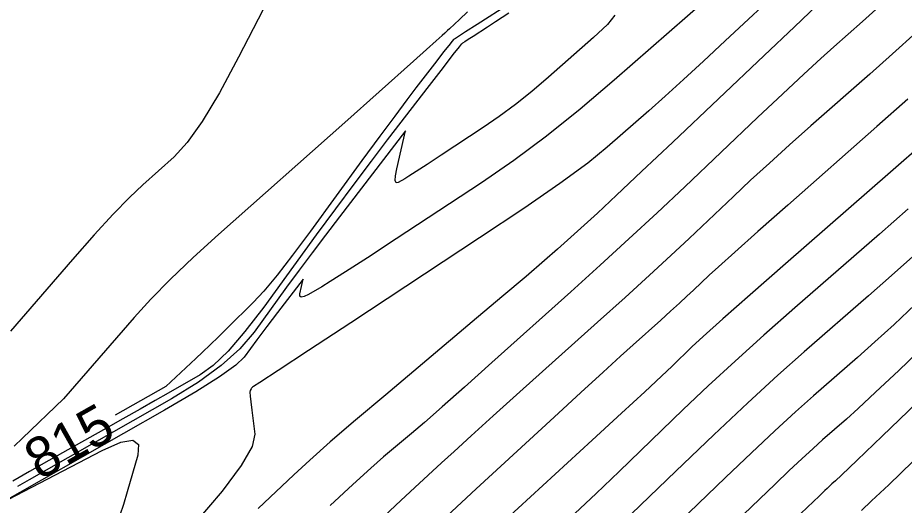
# Model space of a CAD drawing. Extents: x 2079879 to 2092887, y 778083 to 784051.
# Drawn here: x 2084103 to 2084164.7, y 780949.2 to 780983.2 of the extents above; entities that cross this region are included whole.
import ezdxf

# ---------------------------------------------------------------- set-up
doc = ezdxf.new("R2010")
doc.units = 0
doc.layers.add('DT_X_Contour_Major', color=7, linetype='Continuous')
doc.layers.add('DT_X_Contour_Minor', color=7, linetype='Continuous')

msp = doc.modelspace()

# ---------------------------------------------------------------- linework, layer by layer
at = {"layer": 'DT_X_Contour_Major'}
for points in [[(2084139.433, 780985.629), (2084134.941, 780982.739), (2084134.131, 780982.217), (2084133.625, 780981.892), (2084133.424, 780981.763), (2084133.294, 780981.679), (2084133.183, 780981.563), (2084132.95, 780981.28), (2084132.593, 780980.828), (2084132.114, 780980.208), (2084130.671, 780978.332), (2084130.03, 780977.487), (2084129.19, 780976.358), (2084128.151, 780974.945), (2084126.912, 780973.249), (2084123.344, 780968.347), (2084122.09, 780966.657), (2084121.005, 780965.261), (2084120.088, 780964.161), (2084119.339, 780963.357), (2084117.567, 780961.604), (2084116.93, 780960.977), (2084116.347, 780960.41), (2084115.818, 780959.903), (2084115.344, 780959.456), (2084113.259, 780957.508), (2084109.749, 780955.525)], [(2084158.593, 780984.075), (2084157.019, 780982.582), (2084154.905, 780980.576), (2084148.551, 780974.544), (2084146.379, 780972.486), (2084144.627, 780970.836), (2084143.295, 780969.594), (2084142.383, 780968.759), (2084140.513, 780967.079), (2084139.617, 780966.29), (2084138.332, 780965.183), (2084136.657, 780963.759), (2084134.592, 780962.016), (2084128.567, 780956.944), (2084126.474, 780955.17), (2084124.711, 780953.649), (2084123.28, 780952.383), (2084122.18, 780951.37), (2084119.687, 780949.009)], [(2084164.932, 780969.897), (2084162.926, 780968.137), (2084157.034, 780962.99), (2084154.892, 780961.099), (2084152.884, 780959.288), (2084151.009, 780957.555), (2084149.269, 780955.902), (2084144.807, 780951.599), (2084143.204, 780950.059), (2084141.74, 780948.665)], [(2084165.257, 780952.29), (2084163.577, 780950.675), (2084162.383, 780949.54), (2084161.676, 780948.885)]]:
    msp.add_lwpolyline(points, dxfattribs=at)
at = {"layer": 'DT_X_Contour_Minor'}
for points in [[(2084122.087, 780987.746), (2084118.326, 780980.455), (2084116.989, 780977.971), (2084115.798, 780975.988), (2084114.754, 780974.504), (2084113.856, 780973.521), (2084111.656, 780971.566), (2084110.732, 780970.691), (2084109.609, 780969.531), (2084108.287, 780968.088), (2084106.767, 780966.36), (2084102.448, 780961.373)], [(2084156.4, 780985.533), (2084152.191, 780981.588), (2084150.675, 780980.175), (2084149.283, 780978.893), (2084148.015, 780977.745), (2084146.872, 780976.728), (2084143.989, 780974.193), (2084142.623, 780973.084), (2084140.686, 780971.66), (2084138.18, 780969.92), (2084135.103, 780967.864), (2084126.138, 780961.961), (2084123.193, 780960.022), (2084121.082, 780958.634), (2084119.805, 780957.795), (2084119.363, 780957.505), (2084119.296, 780957.467), (2084119.271, 780957.449), (2084119.246, 780957.424), (2084119.221, 780957.39), (2084119.196, 780957.349), (2084119.13, 780957.23), (2084119.119, 780957.112), (2084119.135, 780956.847), (2084119.178, 780956.436), (2084119.247, 780955.877), (2084119.47, 780954.191), (2084119.27, 780953.329), (2084118.506, 780952.007), (2084117.176, 780950.225), (2084115.28, 780947.983)], [(2084150.845, 780984.458), (2084144.469, 780978.852), (2084142.099, 780976.829), (2084139.768, 780974.964), (2084137.478, 780973.259), (2084135.228, 780971.711), (2084129.283, 780967.796), (2084127.288, 780966.487), (2084125.763, 780965.495), (2084124.707, 780964.82), (2084124.121, 780964.463), (2084123.183, 780963.932), (2084122.882, 780963.786), (2084122.682, 780963.744), (2084122.582, 780963.808), (2084122.582, 780963.975), (2084122.819, 780965.004), (2084121.032, 780962.68), (2084120.656, 780962.187), (2084120.292, 780961.706), (2084119.942, 780961.236), (2084119.606, 780960.777), (2084118.725, 780959.567), (2084118.131, 780958.996), (2084117.008, 780958.189), (2084115.356, 780957.147), (2084113.176, 780955.869), (2084101.769, 780949.357), (2084108.834, 780953.06), (2084110.124, 780953.635), (2084110.967, 780953.772), (2084111.364, 780953.472), (2084111.313, 780952.734), (2084110.581, 780950.181), (2084110.315, 780949.297), (2084110.066, 780948.558)], [(2084137.146, 780983.521), (2084136.217, 780982.913), (2084135.655, 780982.548), (2084134.644, 780981.897), (2084134.311, 780981.683), (2084134.069, 780981.527), (2084133.917, 780981.429), (2084133.857, 780981.391), (2084133.818, 780981.366), (2084133.668, 780981.179), (2084133.248, 780980.639), (2084132.557, 780979.744), (2084131.596, 780978.496), (2084128.673, 780974.695), (2084127.543, 780973.212), (2084126.343, 780971.615), (2084125.075, 780969.902), (2084123.737, 780968.075), (2084120.079, 780963.05), (2084118.774, 780961.341), (2084117.603, 780959.984), (2084116.566, 780958.979), (2084115.663, 780958.326), (2084113.435, 780957.054), (2084112.526, 780956.536), (2084111.47, 780955.937), (2084110.268, 780955.255), (2084108.919, 780954.493), (2084105.127, 780952.351), (2084103.787, 780951.594), (2084102.611, 780950.929)], [(2084134.264, 780983.621), (2084133.699, 780983.093), (2084132.996, 780982.436), (2084132.858, 780982.307), (2084132.681, 780982.142), (2084132.495, 780981.973), (2084132.07, 780981.591), (2084131.404, 780980.996), (2084130.499, 780980.187), (2084125.717, 780975.915), (2084116.935, 780968.11), (2084115.156, 780966.494), (2084113.585, 780964.993), (2084112.221, 780963.605), (2084111.064, 780962.332), (2084106.147, 780956.655), (2084103.28, 780953.911), (2084102.708, 780953.358)], [(2084162.673, 780983.771), (2084161.747, 780982.945), (2084159.749, 780981.181), (2084158.855, 780980.377), (2084157.674, 780979.286), (2084156.205, 780977.91), (2084154.448, 780976.249), (2084149.378, 780971.436), (2084147.457, 780969.625), (2084145.495, 780967.802), (2084143.493, 780965.967), (2084141.45, 780964.12), (2084135.948, 780959.177), (2084134.052, 780957.479), (2084132.489, 780956.09), (2084131.26, 780955.012), (2084130.365, 780954.244), (2084128.422, 780952.608), (2084127.524, 780951.824), (2084126.285, 780950.699), (2084124.707, 780949.232)], [(2084144.521, 780983.386), (2084143.998, 780982.737), (2084143.039, 780981.831), (2084139.902, 780979.072), (2084138.735, 780978.077), (2084137.588, 780977.159), (2084136.461, 780976.32), (2084135.354, 780975.558), (2084132.428, 780973.632), (2084131.446, 780972.987), (2084130.696, 780972.499), (2084130.176, 780972.167), (2084129.888, 780971.991), (2084129.426, 780971.73), (2084129.291, 780971.715), (2084129.233, 780971.867), (2084129.25, 780972.186), (2084129.343, 780972.67), (2084129.954, 780975.321), (2084125.348, 780969.331), (2084124.378, 780968.062), (2084123.441, 780966.821), (2084122.539, 780965.609), (2084121.671, 780964.426), (2084119.402, 780961.308), (2084118.405, 780960.141), (2084117.116, 780958.979), (2084115.536, 780957.82), (2084113.664, 780956.666), (2084108.283, 780953.594), (2084106.436, 780952.54), (2084104.93, 780951.682), (2084103.765, 780951.019), (2084102.941, 780950.552)], [(2084165.487, 780982.172), (2084163.828, 780980.685), (2084162.249, 780979.284), (2084158.149, 780975.665), (2084156.659, 780974.34), (2084155.265, 780973.08), (2084153.965, 780971.885), (2084152.762, 780970.755), (2084149.679, 780967.829), (2084148.414, 780966.641), (2084146.931, 780965.272), (2084145.231, 780963.722), (2084143.313, 780961.992), (2084137.907, 780957.136), (2084136.046, 780955.462), (2084134.518, 780954.082), (2084133.321, 780952.997), (2084132.457, 780952.206), (2084130.594, 780950.49), (2084129.618, 780949.578), (2084128.088, 780948.13)], [(2084164.898, 780977.522), (2084162.752, 780975.623), (2084156.55, 780970.149), (2084154.463, 780968.304), (2084152.855, 780966.874), (2084151.726, 780965.86), (2084151.076, 780965.262), (2084149.979, 780964.221), (2084149.529, 780963.799), (2084149.002, 780963.312), (2084148.397, 780962.761), (2084147.715, 780962.145), (2084145.792, 780960.418), (2084144.908, 780959.617), (2084143.695, 780958.511), (2084142.155, 780957.098), (2084140.288, 780955.379), (2084134.87, 780950.387), (2084132.82, 780948.488)], [(2084166.093, 780974.536), (2084163.691, 780972.437), (2084156.387, 780966.056), (2084153.926, 780963.9), (2084152.02, 780962.218), (2084150.669, 780961.008), (2084149.874, 780960.272), (2084148.494, 780958.941), (2084147.759, 780958.244), (2084146.589, 780957.152), (2084144.985, 780955.666), (2084142.946, 780953.784), (2084136.93, 780948.24)], [(2084165.242, 780966.579), (2084163.772, 780965.257), (2084162.162, 780963.838), (2084157.682, 780959.924), (2084155.864, 780958.304), (2084153.771, 780956.381), (2084151.402, 780954.153), (2084148.758, 780951.622), (2084138.903, 780942.118)], [(2084165.42, 780963.222), (2084163.952, 780961.845), (2084162.611, 780960.617), (2084161.397, 780959.538), (2084158.329, 780956.857), (2084157.084, 780955.748), (2084155.65, 780954.431), (2084154.028, 780952.905), (2084152.217, 780951.172), (2084147.137, 780946.272)], [(2084166.268, 780960.561), (2084164.268, 780958.639), (2084162.662, 780957.111), (2084161.45, 780955.977), (2084160.632, 780955.238), (2084158.976, 780953.791), (2084158.304, 780953.192), (2084157.53, 780952.481), (2084156.654, 780951.658), (2084155.677, 780950.722), (2084152.934, 780948.077)], [(2084165.521, 780956.374), (2084163.116, 780954.056), (2084161.372, 780952.377), (2084160.289, 780951.338), (2084159.867, 780950.938), (2084159.623, 780950.724), (2084159.524, 780950.636), (2084159.41, 780950.531), (2084159.281, 780950.41), (2084159.136, 780950.272), (2084158.732, 780949.882), (2084158.336, 780949.504), (2084157.449, 780948.662)]]:
    msp.add_lwpolyline(points, dxfattribs=at)

# ---------------------------------------------------------------- texts
at = {"layer": 'DT_X_Contour_Major'}
msp.add_text('815', height=2.8, rotation=29.46352, dxfattribs=at).set_placement((2084104.488, 780950.945))

doc.saveas('drawing.dxf')
